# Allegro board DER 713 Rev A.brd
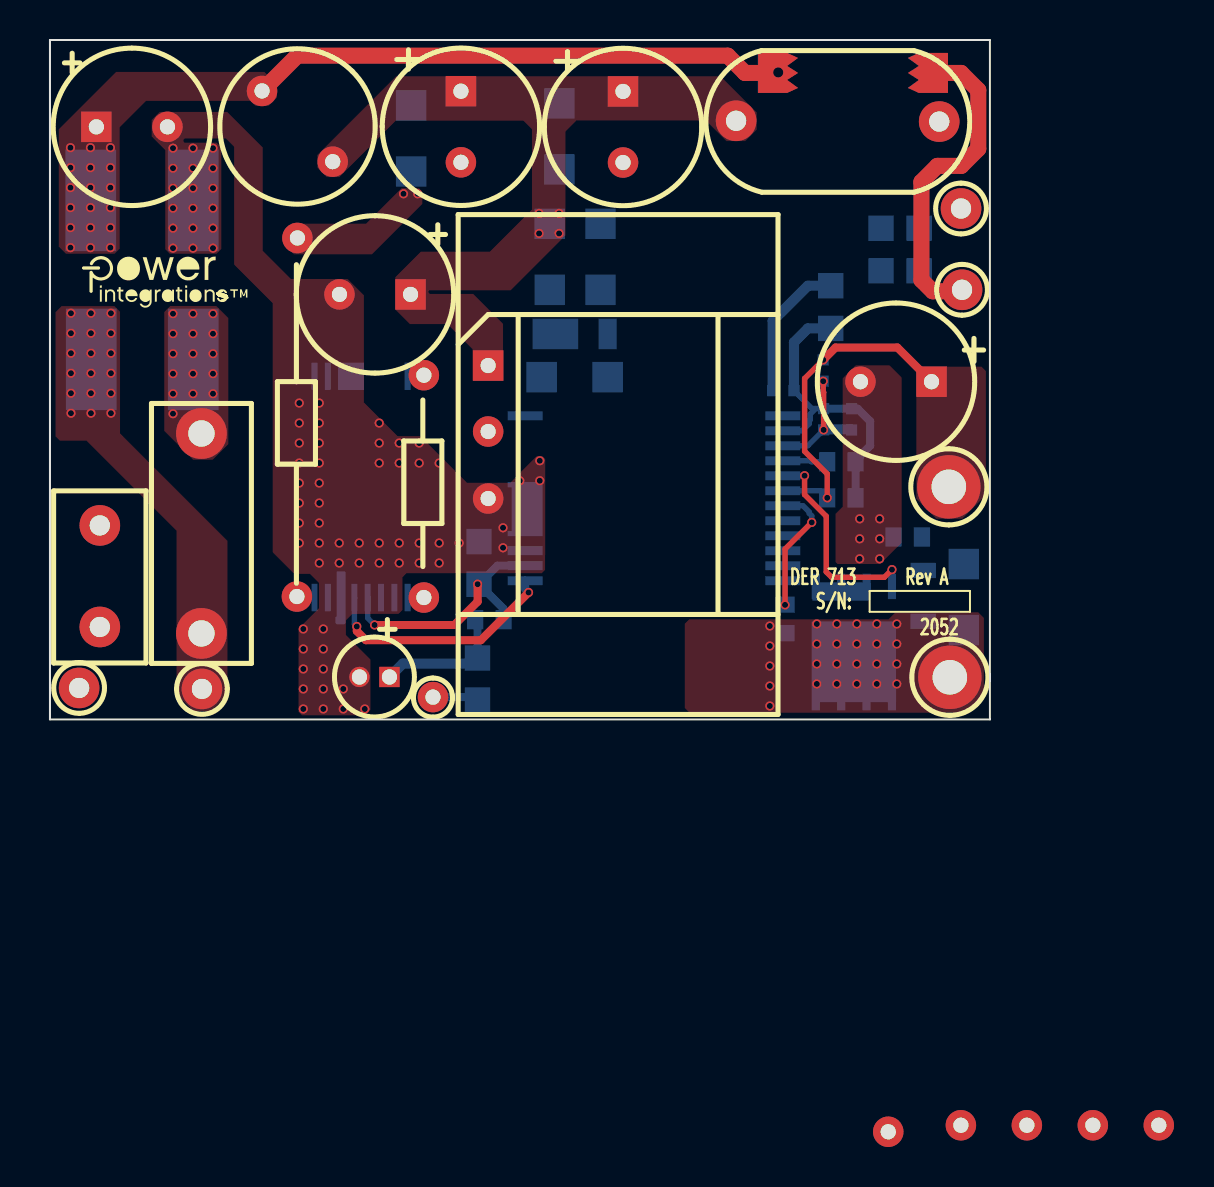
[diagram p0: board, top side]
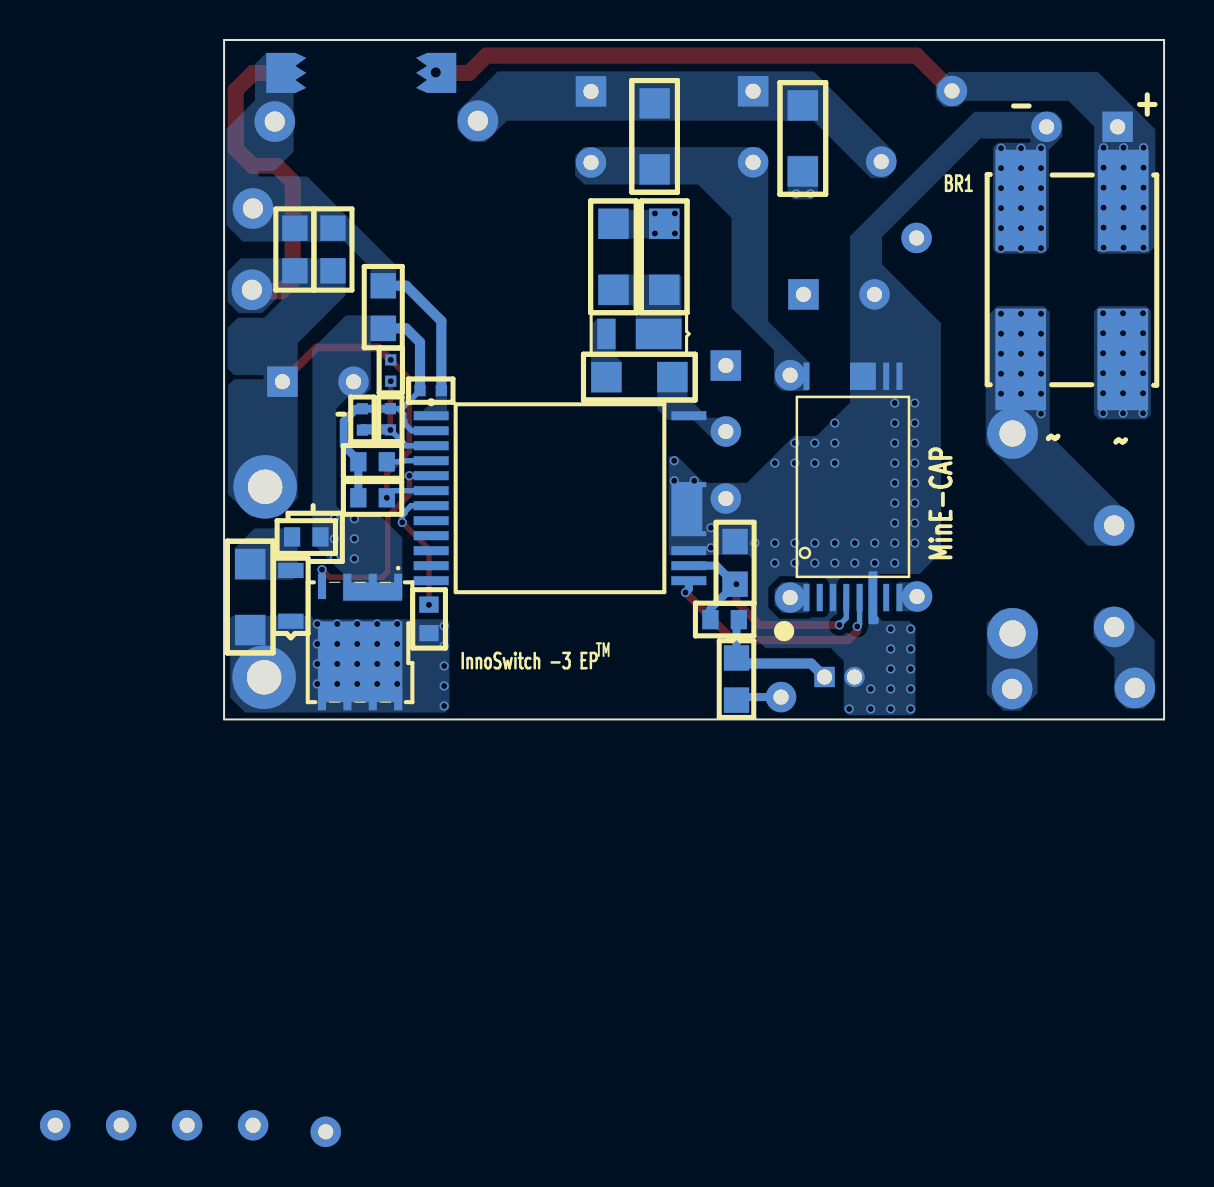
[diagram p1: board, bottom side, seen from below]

Outline 47.02 x 33.98 mm; copper layers: TOP, BOTTOM. Coordinates in mm from the lower left corner of the outline.
Outline path: 0,33.98 0,0 47.02,0 47.02,33.98 0,33.98

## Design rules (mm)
constraint set DEFAULT: min track width 0.508

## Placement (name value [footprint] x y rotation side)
BR1  Z4DGP406L-HF  [PI_SM_D_Z4D]  2.07 26.01 180 bottom
C1  0.1 uF  [PINPXCAPRAD5X13X11P1MM040]  7.58 14.3 270 top
C2  22 uF  [PIPOLCAPCLYD320LS140030]  2.32 29.64 0 top
C3  1 nF  [PINPYCAPRAD540X290LS400040]  34.33 31.19 0 top
C4  1000 pF  [PISMC1206]  25 24.79 270 bottom
C6  4.7 uF  [PISMC0805]  21.46 6.76 90 bottom
C7  1000 pF  [PISMC0603]  43.62 9.13 180 bottom
C8  820 uF  [PIPOLCAPCLYD320LS140030]  44.1 16.89 180 top
C10  2.2 uF  [PISMC0603]  40.31 12.89 180 bottom
C11  1 uF  [PISMC0603]  40.31 11.08 180 bottom
C12  1000 pF  [PISMR0402]  37.22 16.44 180 bottom
C13  1000 pF  [PISMR0402]  38.7 14.48 90 bottom
C16  22 uF  [PISMC0805]  43.48 22.44 90 bottom
C17  22 uF  [PISMC0805]  41.58 22.44 90 bottom
C18  22 uF  [PIPOLCAPCLYD320LS140030]  18.04 21.26 180 top
C19  33 uF  [PIPOLCAPCLYD320LS140030]  28.67 31.41 270 top
C21  22 uf  [PIPOLCAP4P0X11P0XLS1P5D030]  16.98 2.12 180 top
C23  33 uF  [PIPOLCAPCLYD320LS140030]  20.56 31.42 270 top
D1  DFLR1800-7  [PISMDDFLR120012]  25.26 19.28 180 bottom
D2  BAV20WS-7-F  [PISMDSOD323]  21.39 3.07 270 bottom
D4  BAV19WS  [PISMSOD323]  43.68 4.91 90 bottom
F1  3.15 A  [PI_RST_MICROFUSE]  2.5 4.62 90 top
FL1  Hole_70mils  [PI_HOLE_70MIL]  44.97 11.61 0 top
FL2  Hole_70mils  [PI_HOLE_70MIL]  45.02 2.08 0 top
FL3  Hole_30mils  [PI_HOLE_30MIL]  19.16 1.12 0 top
GND  BLK  [PITPKEYSTONE100X100]  45.58 25.55 0 top
L  BLK  [PITPKEYSTONE100X100]  1.46 1.57 0 top
L1  47 uH  [PICHOKETOKINVD345H453LS197D030]  10.61 31.43 315 top
N  WHT  [PITPKEYSTONE100X100]  7.6 1.53 90 top
NOREF  -  []  -150.78 54.23 0 top
NOREF#2  -  []  0 0 90 top
NOREF#3  -  []  1.05 23.06 0 top
NOREF#4  -  []  -228.6 -144.78 0 top
NOREF#5  -  []  0 0 0 top
Q1  AON6220  [PISMPQFN5X6B]  38.31 6.65 0 bottom
R3  2 M  [PISMR1206]  18.07 30.71 270 bottom
R4  1.8 M  [PI18WVRESD80LS100D030]  12.38 13.08 270 top
R5  24  [PISMR1206]  27.9 17.12 180 bottom
R7  470 k  [PISMR1206]  27.54 24.79 270 bottom
R8  3 k  [PISMR0603]  21.27 4.99 0 bottom
R11  10  [PISMR1206]  45.72 4.47 90 bottom
R12  47  [PISMR0603]  36.78 4.32 90 bottom
R14  0.009  [PISMR0805]  39.06 19.56 90 bottom
R15  169.0 k  [PISMR0402]  38.69 17.98 270 bottom
R16  11.5 k  [PISMR0402]  40.1 15.54 270 bottom
R24  3.9 M  [PISMR1206]  25.49 30.81 270 bottom
R27  1 M  [PI18WVRESD80LS100D030#2]  18.71 13.72 270 top
SG1  6.5mm gap  [PI_SPARK_GAP_6P5MM#2]  39.66 32.33 0 bottom
SG2  6.5mm gap  [PI_SPARK_GAP_6P5MM]  40.68 32.33 0 top
T2  ATQ25/16  [PI_BOBBIN_ATQ25_H_8P]  28.42 12.75 0 top
U1  INN3679C-H606  [PI_IC_INSOP_24D]  36.66 15.19 180 bottom
U4  MIN1072M  [PI_SM_MINSOP16A_1]  17.89 6.1 180 bottom
UNK20V  RED  [PITPKEYSTONE100X100]  45.63 21.49 0 top

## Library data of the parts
BR1 = DISCRETE BRIDGE_+~~-
C1 = CAP NP: alternate symbols: (pinpxcaprad5x13x11p1mm040h)
C2 C18 = CAP POL: alternate symbols: (pipolcapclyd320ls140030h630)
C3 = CAP NP: alternate symbols: (pinpycaprad540x290ls400040h,pinpycaprad500x220ls400040)
C4 C6 C7 C16 C17 = CAP NP
C8 C19 C23 = CAP POL
C10 C11 = CAP NP: alternate symbols: (pismc0603_1)
C12 C13 = CAP NP: alternate symbols: (pismr0402_1); room: 2
C21 = CAP POL: alternate symbols: (pipolcap4p0x12p5xls1p5d030h)
D1 = DIODE: room: 1
D2 = DIODE
D4 = DIODE: room: 2
F1 = FUSE: alternate symbols: (pirstmicrofusehoz); room: 1
FL1-FL3 = FlyingLead: room: 2
GND L = TESTPOINT: alternate symbols: (TP_TH_CR2_D1_1)
L1 = INDUCTOR: alternate symbols: (pichoketokinvd345h453ls197d030H)
N UNK20V = TESTPOINT
Q1 = FET_N_SGD_123_4_5678: room: 2
R3 R5 R7 R8 R11 R14 R24 = R
R4 R27 = R: alternate symbols: (pi18wresd080ls300d030)
R12 = R: alternate symbols: (pismr0603_1); room: 2
R15 R16 = R: room: 2
SG1 SG2 = SPARK_GAP
T2 = BATQ25_8P/GENERIC
U1 = Inno3EP_P15
U4 = MinE-CAP

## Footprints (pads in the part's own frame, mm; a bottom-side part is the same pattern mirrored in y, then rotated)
PI18WVRESD80LS100D030
  round 1.524 hole 0.762: 1(-11,0) 2(6.934,-0.025)
PI18WVRESD80LS100D030#2
  round 1.524 hole 0.762: 1(-3.5,0) 2(7.62,0)
PI_BOBBIN_ATQ25_H_8P
  rect 1.524x1.524 hole 0.762: 1(-6.5,4.95)
  round 1.524 hole 0.762: 2(-6.5,1.65) 3(-6.5,-1.701) 4(13.515,-33.373) 5(27.049,-33.046) 6(23.749,-33.046) 7(20.449,-33.046) 8(17.149,-33.046)
PI_HOLE_30MIL
  round 1.524 hole 0.762: 1(0,0)
PI_HOLE_70MIL
  round 3.175 hole 1.727: 1(0,0.025)
PI_IC_INSOP_24D
  rect 1.75x0.45 smd: 1(0,0) 2(0,-0.75) 3(0,-1.5) 4(0,-2.25) 5(0,-3) 6(0,-3.75) 7(0,-4.5) 8(0,-5.25) 9(0,-6) 10(0,-6.75) 11(0,-7.5) 12(0,-8.25) 13(12.89,-8.25) 14(12.89,-7.5) 15(12.89,-6.75) 24(12.89,0)
  custom 0.438x0.438 smd: 16(12.89,-4.67)
PI_RST_MICROFUSE
  round 2.032 hole 1.016: 1(0,0) 2(5.08,0)
PI_SM_D_Z4D
  rect 2.54x5.08 smd: 1(0.025,-0.051) 2(0,-8.001) 3(-5.105,-8.001) 4(-5.105,-0.051)
PI_SM_MINSOP16A_1
  rect 0.3x1.369 smd: 1(0,0) 2(0.665,0) 3(1.33,0) 4(1.995,0) 5(2.66,0) 6(3.325,0) 7(3.99,0) 8(4.655,0) 9(4.655,11.067) 10(3.99,11.067) 16(0,11.067)
  rect 1.293x1.369 smd: 11(2.829,11.067)
PI_SPARK_GAP_6P5MM
  custom 0.5x0.5 smd: 1(-4.25,0) 2(3.25,0)
PI_SPARK_GAP_6P5MM#2
  custom 0.5x0.5 smd: 1(-3.25,0) 2(4.25,0)
PICHOKETOKINVD345H453LS197D030
  round 1.524 hole 0.762: 1(0,0) 2(5.001,0)
PINPXCAPRAD5X13X11P1MM040
  round 2.54 hole 1.321: 1(0,0) 2(10,0)
PINPYCAPRAD540X290LS400040
  round 2.032 hole 1.016: 1(0,-1.25) 2(10.16,-1.29)
PIPOLCAP4P0X11P0XLS1P5D030
  rect 1.016x1.016 hole 0.762: 1(0,0)
  round 1.016 hole 0.762: 2(1.5,0)
PIPOLCAPCLYD320LS140030
  rect 1.524x1.524 hole 0.762: 1(0,0)
  round 1.524 hole 0.762: 2(3.556,0)
PISMC0603
  rect 0.813x0.965 smd: 1(0,0) 2(1.422,0)
PISMC0805
  rect 1.27x1.27 smd: 1(0,0) 2(2.134,0)
PISMC1206
  rect 1.524x1.524 smd: 1(0,0) 2(3.302,0)
PISMDDFLR120012
  rect 2.286x1.524 smd: 1(-0.025,0)
  rect 0.914x1.524 smd: 2(-2.642,0)
PISMDSOD323
  rect 1.27x1.27 smd: 1(0,0) 2(2.108,0)
PISMPQFN5X6B
  rect 0.406x1.27 smd: 1(0,0) 2(1.27,0) 3(2.54,0) 4(3.81,0)
  rect 0.406x1.219 smd: 5(3.81,5.588) 6(2.54,5.588) 7(1.27,5.588) 8(0,5.588)
PISMR0402
  rect 0.559x0.559 smd: 1(0,0) 2(1.067,0)
PISMR0603
  rect 0.813x0.965 smd: 1(0,0) 2(1.422,0)
PISMR0805
  rect 1.27x1.27 smd: 1(0,0) 2(2.134,0)
PISMR1206
  rect 1.524x1.524 smd: 1(0,0) 2(3.302,0)
PISMSOD323
  rect 0.762x1.27 smd: 1(0,0) 2(2.54,0)
PITPKEYSTONE100X100
  round 2.032 hole 1.016: 1(0,0)

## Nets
D: D4.1 FL2.1 Q1.5 Q1.6 Q1.7 Q1.8 R11.1 R12.1
NC8: U1.8
NC9: U1.9
NC10: U1.10
NC11: U1.11
NC12: U1.12
S: C7.2 C8.2 C10.1 C11.1 C12.1 C13.2 Q1.1 Q1.2 Q1.3(S3) R14.1 R16.1 U1.2
VTOP: R4.2 U4.8
N10805923: BR1.4 C2.2 C6.2 C18.2 C21.2 T2.3 U1.15 U1.16 U4.3 U4.9 U4.10 U4.11
N10806149: C6.1 R8.2 U1.14 U4.4
N10808843: C3.2 C12.2 C16.2 C17.2 GND.1 R14.2 SG1.2 U1.1
N10813018: R3.2 R4.1
N10840366: BR1.1 C2.1 L1.1 SG1.1 SG2.1
N10873526: R12.2 U1.7
N10897256: C13.1 R15.2 R16.2 U1.3
N10950053: C21.1 D2.1 R8.1
N10961861: C3.1 C4.1 C18.1 C19.1 C23.1 L1.2 R3.1 R7.1 R24.1 T2.1
N10998999: C8.1 C11.2 C16.1 C17.1 FL1.1 R15.1 SG2.2 U1.6 UNK20V.1
N11099981: BR1.3(AC2) C1.1 F1.2
N11100037: BR1.2 C1.2 N.1
N11139529: C4.2 D1.1 R7.2
N11156493: C7.1 D4.2 R11.2
N12473754: C19.2 C23.2 R24.2 R27.1 U4.16
N12473992: U1.13(VPIN) U4.5
N12493844: R5.2 T2.2 U1.24
N12496023: Q1.4 U1.5
N12509547: D1.2 R5.1
N12525421: F1.1 L.1
N12537489: R27.2 U4.1
N12549108: D2.2 FL3.1
N12562988: C10.2 U1.4

Pads without a net: T2 4 5 6 7 8; U4 2 6 7

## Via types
v1: diameter 0.457, hole 0.305, TOP to BOTTOM, 175 vias
v2: diameter 0.813, hole 0.508, TOP to BOTTOM, 1 via

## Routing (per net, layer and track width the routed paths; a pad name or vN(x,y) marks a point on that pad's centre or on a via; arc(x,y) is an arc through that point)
D:
  vias: v1(36.01,4.67) v1(36.01,3.67) v1(36.01,2.67) v1(36.01,1.67) v1(36.01,0.67) v1(38.36,4.78) v1(38.36,3.78) v1(38.36,2.78) v1(38.36,1.78) v1(39.36,4.78) v1(39.36,3.78) v1(39.36,2.78) v1(39.36,1.78) v1(40.36,4.78) v1(40.36,3.78) v1(40.36,2.78) v1(40.36,1.78) v1(41.36,4.78) v1(41.36,3.78) v1(41.36,2.78) v1(41.36,1.78) v1(42.36,4.78) v1(42.36,3.78) v1(42.36,2.78) v1(42.36,1.78)
S: length 15.5
  BOTTOM w0.27: C13.2 38.31,15.55 ; 38.31,15.55 38.12,15.55 C12.1 ; 38.31,15.55 38.04,15.28 38.04,14.99 37.98,14.94 37.98,14.79 37.64,14.44 U1.2
  BOTTOM w0.4: C11.1 C10.1 40.31,12.96 41.03,13.69 41.03,14.92 40.41,15.54 R16.1 38.71,15.54 C13.2
  BOTTOM w0.508: R14.1 37.92,19.56 37.22,18.86 C12.1
  vias: v1(40.51,10.03) v1(40.51,9.03) v1(40.51,8.03) v1(41.51,10.03) v1(41.51,9.03) v1(41.51,8.03)
N10805923:
  vias: v1(6.16,28.57) v1(6.16,27.57) v1(6.16,26.57) v1(6.16,25.57) v1(6.16,24.57) v1(6.16,23.57) v1(7.16,28.57) v1(7.16,27.57) v1(7.16,26.57) v1(7.16,25.57) v1(7.16,24.57) v1(7.16,23.57) v1(8.16,28.57) v1(8.16,27.57) v1(8.16,26.57) v1(8.16,25.57) v1(8.16,24.57) v1(8.16,23.57) v1(12.47,15.82) v1(12.47,14.82) v1(12.47,13.82) v1(12.47,12.82) v1(12.47,11.82) v1(12.47,10.82) v1(12.47,9.82) v1(12.47,8.82) v1(12.68,4.52) v1(12.68,3.52) v1(12.68,2.52) v1(12.68,1.52) v1(12.68,0.52) v1(13.47,15.82) v1(13.47,14.82) v1(13.47,13.82) v1(13.47,12.82) v1(13.47,11.82) v1(13.47,10.82) v1(13.47,9.82) v1(13.47,8.82) v1(13.47,7.82) v1(13.68,4.52) v1(13.68,3.52) v1(13.68,2.52) v1(13.68,1.52) v1(13.68,0.52) v1(14.47,8.82) v1(14.47,7.82) v1(14.68,1.52) v1(14.68,0.52) v1(15.47,8.82) v1(15.47,7.82) v1(15.75,0.52) v1(16.47,14.82) v1(16.47,13.82) v1(16.47,12.82) v1(16.47,8.82) v1(16.47,7.82) v1(17.47,13.82) v1(17.47,12.82) v1(17.47,8.82) v1(17.47,7.82) v1(18.47,13.82) v1(18.47,12.82) v1(18.47,8.82) v1(18.47,7.82) v1(19.47,12.82) v1(19.47,8.82) v1(19.47,7.82) v1(20.47,8.82) v1(22.67,9.59) v1(22.67,8.59) v1(23.5,11.94) v1(24.5,12.94) v1(24.5,11.94)
N10806149: length 13.1
  TOP w0.4: v1(16.24,4.72) 20.23,4.72 21.4,5.89 v1(21.4,6.76)
  BOTTOM w0.27: v1(16.24,4.72) 15.9,5.07 U4.4 ; C6.1 v1(21.4,6.76)
  BOTTOM w0.4: U1.14 22.39,7.69 C6.1 22.69,5.53 R8.2
N10808843: length 7.1
  BOTTOM w0.508: C12.2 36.16,19.93 37.92,21.69 R14.2
N10813018:
  vias: v1(17.69,26.29) v1(18.4,26.29)
N10840366: length 27
  TOP w0.8: SG2.1 34.77,32.33 33.91,33.2 12.37,33.2 L1.1 10.67,31.37
  vias: v1(1.03,28.6) v1(1.03,27.6) v1(1.03,26.6) v1(1.03,25.6) v1(1.03,24.6) v1(1.03,23.6) v1(2.03,28.6) v1(2.03,27.6) v1(2.03,26.6) v1(2.03,25.6) v1(2.03,24.6) v1(2.03,23.6) v1(3.03,28.6) v1(3.03,27.6) v1(3.03,26.6) v1(3.03,25.6) v1(3.03,24.6) v1(3.03,23.6) v2(36.43,32.36)
N10873526: length 6.7
  TOP w0.27: v1(36.78,5.73) 36.78,8.52 v1(38.11,9.86)
  BOTTOM w0.27: U1.7 37.67,10.69 37.98,10.38 37.98,10.32 38.11,10.19 v1(38.11,9.86)
  BOTTOM w0.508: R12.2 v1(36.78,5.73)
N10897256: length 6.2
  TOP w0.27: v1(38.69,16.92) 38.69,16.37 38.7,16.36 v1(38.7,14.48)
  BOTTOM w0.27: U1.3 36.66,13.69 37.91,13.69 v1(38.7,14.48)
  BOTTOM w0.508: R16.2 40.07,14.5 38.73,14.5 v1(38.7,14.48)
N10950053: length 6.8
  BOTTOM w0.4: D2.1 21.39,4.88 R8.1
  BOTTOM w0.508: D2.1 21.11,2.79 17.66,2.79 C21.1
N10961861:
  vias: v1(24.47,25.31) v1(24.47,24.31) v1(25.47,25.31) v1(25.47,24.31)
N10998999: length 33
  TOP w0.27: v1(38.88,11.08) 38.88,12.28 37.75,13.41 37.75,17.05 v1(38.69,17.98)
  TOP w0.4: C8.1 42.39,18.6 39.3,18.6 v1(38.69,17.98)
  TOP w0.8: UNK20V.1 45.55,21.41 44.16,21.41 43.6,21.98 43.6,26.89 44.4,27.69 45.59,27.69 46.44,28.54 46.44,31.47 45.58,32.33 SG2.2
  BOTTOM w0.27: v1(38.88,11.08) 38.53,11.44 U1.6
N11099981:
  vias: v1(6.16,20.29) v1(6.16,19.29) v1(6.16,18.29) v1(6.16,17.29) v1(6.16,16.29) v1(6.16,15.29) v1(7.16,20.29) v1(7.16,19.29) v1(7.16,18.29) v1(7.16,17.29) v1(7.16,16.29) v1(8.16,20.29) v1(8.16,19.29) v1(8.16,18.29) v1(8.16,17.29) v1(8.16,16.29)
N11100037:
  vias: v1(1.05,20.32) v1(1.05,19.32) v1(1.05,18.32) v1(1.05,17.32) v1(1.05,16.32) v1(1.05,15.32) v1(2.05,20.32) v1(2.05,19.32) v1(2.05,18.32) v1(2.05,17.32) v1(2.05,16.32) v1(2.05,15.32) v1(3.05,20.32) v1(3.05,19.32) v1(3.05,18.32) v1(3.05,17.32) v1(3.05,16.32) v1(3.05,15.32)
N12473992: length 12.2
  TOP w0.4: v1(15.35,4.65) 15.35,4.42 15.81,3.96 21.56,3.96 v1(23.94,6.35)
  BOTTOM w0.27: U4.5 15.23,4.77 v1(15.35,4.65)
  BOTTOM w0.4: U1.13 23.77,6.52 v1(23.94,6.35)
N12496023: length 10.7
  TOP w0.27: v1(37.75,12.19) 37.75,11.25 38.84,10.16 38.84,7.38 39.11,7.11 41.74,7.11 v1(42.12,7.49)
  BOTTOM w0.27: Q1.4 v1(42.12,7.49) ; U1.5 v1(37.75,12.19)
N12549108: length 2.3
  BOTTOM w0.4: D2.2 21.24,1.12 FL3.1
N12562988: length 2.2
  BOTTOM w0.27: U1.4 38.04,12.94 38.09,12.89 C10.2

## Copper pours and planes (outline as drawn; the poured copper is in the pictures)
D on BOTTOM (solid shape): 42.33,0.86 38.11,0.86 38.11,4.9 42.33,4.9
D on TOP: 45.96,0.33 46.72,1.09 46.72,5.08 46.44,5.36 42.3,5.36 41.95,5.01 31.98,5.01 31.76,4.79 31.76,0.57 32,0.33
D on BOTTOM: 46.59,5.18 46.72,5.05 46.72,1.09 45.97,0.34 35.96,0.34 35.75,0.56 35.75,4.88 35.87,5.01 42.53,5.01 42.71,5.18
S on BOTTOM (solid shape): 41.06,5.94 38.14,5.94 38.14,6.86 41.06,6.86
S on TOP: 39.66,17.06 39.66,10.64 39.3,10.28 39.3,7.88 39.41,7.77 41.54,7.77 42.48,8.71 42.61,8.84 42.61,17.11 42.01,17.71 40.31,17.71
S on BOTTOM: 38.11,5.94 38.14,5.92 41.08,5.92 41.08,7.29 42.61,8.81 42.61,18.53 40.93,20.21 38.45,20.21 38.41,20.17 38.41,18.92 39.68,18.92 39.68,16.54 40.09,16.13 40.83,16.13 41.41,15.54 41.41,10.69 40.93,10.21 39.23,10.21 38.11,9.09
VTOP on BOTTOM: 13.37,6.78 13.37,5.41 12.15,5.41 11.69,5.87 11.69,6.45 12.1,6.86 13.29,6.86
N10805923 on BOTTOM (solid shape): 14.79,7.35 14.79,4.82 14.73,4.76 14.35,4.76 14.27,4.84 14.27,5.1 14.35,5.17 14.35,7.41 14.73,7.41
N10805923 on TOP: 24.77,13.03 24.77,8.23 24.77,8.23 24.77,7.49 24.6,7.31 17.84,7.31 17.63,7.11 17.63,5.47 17.43,5.28 15.13,5.28 14.81,4.95 14.81,4.23 16.03,3 16.03,0.47 15.77,0.2 12.61,0.2 12.44,0.38 12.44,4.54 13.46,5.56 13.46,6.82 13.01,7.28 12.23,7.28 11.14,8.36 11.14,20.81 11.15,20.81 9.81,22.15 9.21,22.75 9.21,28.64 8.8,29.06 6.75,29.06 6.68,28.98 6.68,28.91 6.75,28.84 8.34,28.84 8.57,28.61 8.57,23.53 8.33,23.29 6,23.29 5.77,23.52 5.77,28.48 5.09,29.16 5.09,29.98 5.49,30.39 8.87,30.39 10.64,28.61 10.64,23.44 12.06,22.03 14.89,22.03 15.7,21.22 15.7,15.85 17.38,14.17 18.32,14.17 18.32,14.17 18.53,14.17 20.86,11.84 23.02,11.84 24.34,13.16 24.65,13.16
N10805923 on BOTTOM: 15.71,15.85 17.38,14.17 18.53,14.17 20.86,11.84 23.02,11.84 24.34,13.16 24.77,13.16 24.77,8.23 20.79,8.23 20.48,7.93 20.48,4.11 19.93,3.56 16.67,3.56 16.03,2.92 16.03,0.47 15.77,0.2 12.61,0.2 12.44,0.38 12.44,4.61 12.75,4.93 14.1,4.93 14.35,5.17 14.35,7.16 14.23,7.28 12.23,7.28 11.16,8.35 11.16,19.81 11.67,20.32 14.11,22.76 14.11,24.13 9.56,28.68 9.18,29.05 6.74,29.05 6.67,28.98 6.67,28.92 6.74,28.84 8.33,28.84 8.56,28.61 8.56,23.52 8.33,23.29 6.02,23.29 5.77,23.55 5.77,28.48 5.09,29.16 5.09,29.98 5.5,30.39 9.49,30.39 15.71,24.17
N10808843 on BOTTOM: 35.87,15.01 37.45,15.01 37.45,15.39 37.12,15.39 36.43,16.08 36.43,16.71 35.87,16.71
N10808843 on BOTTOM: 46.09,23.9 46.9,24.71 46.9,29.54 45.48,30.96 45.48,32.78 44.93,33.33 43.66,33.33 43.55,33.22 43.55,28.4 44.49,27.46 45.22,27.46 45.32,27.36 45.32,27.23 45.25,27.15 42.86,27.15 38.41,22.71 38.41,21.06 39.68,21.06 39.68,22.58 41.01,23.9
N10813018 on TOP: 11.82,24.49 11.82,23.65 12.2,23.27 16.11,23.27 18.63,25.78 18.63,26.39 18.45,26.57 17.59,26.57 15.81,24.79 12.13,24.79
N10813018 on BOTTOM: 18.81,28.19 18.83,28.17 18.83,26.29 18.55,26.01 17.61,26.01 17.31,26.31 17.31,28.17 17.33,28.19
N10840366 on TOP: 3.49,23.55 3.49,29.62 4.81,30.94 9.96,30.94 9.96,30.93 10.03,30.93 10.27,30.7 10.95,30.7 11.36,31.11 11.36,31.75 11.32,31.79 10.73,32.38 3.31,32.38 0.44,29.51 0.44,23.65 0.79,23.3 0.79,23.29 3.24,23.29
N10840366 on BOTTOM: 0.44,23.65 0.44,29.51 3.31,32.38 10.78,32.38 11.42,31.75 11.42,31.04 11.01,30.63 10.28,30.63 9.98,30.94 4.79,30.94 3.49,29.64 3.49,23.55 3.24,23.29 0.8,23.29
N10961861 on TOP: 22.67,16.94 21.14,16.94 21.14,18.52 19.89,19.77 18.01,19.77 17.28,20.5 17.28,22.12 18.55,23.39 22.01,23.39 24.11,25.5 24.11,29.51 23.68,29.95 17.3,29.95 14.48,27.12 13.85,27.12 13.38,27.59 13.38,28.23 17.32,32.17 33.54,32.17 35.36,30.35 35.36,29.5 34.78,28.92 33.85,28.92 32.81,29.96 26.34,29.96 25.79,29.41 25.79,24.21 23.05,21.46 18.98,21.46 18.93,21.41 18.93,21.36 19.01,21.29 21.17,21.29 22.67,19.79
N10961861 on BOTTOM: 24.42,25.48 28.13,25.48 28.25,25.35 28.25,24.16 28.15,24.05 24.37,24.05 24.29,24.13 24.29,25.35
N10961861 on BOTTOM: 33.32,32.41 35.36,30.38 35.36,29.52 34.72,28.88 33.93,28.88 32.87,29.95 18.07,29.95 18.07,29.94 17.54,29.94 14.67,27.07 13.88,27.07 13.42,27.53 13.42,28.3 17.53,32.41
N10998999 on TOP: 46.82,17.42 46.6,17.64 43.34,17.64 43.34,11.04 44.35,10.04 45.64,10.04 46.82,11.22
N10998999 on BOTTOM: 43.34,18.82 43.34,11.05 44.25,10.15 45.71,10.15 46.82,11.26 46.82,16.71 46.52,17.02 45.09,17.02 45.04,17.07 45.04,17.17 45.09,17.22 46.52,17.22 46.85,17.55 46.85,19.58 46.34,20.09 45.02,20.09 44.15,20.96 44.15,21.35 44.24,21.44 44.29,21.44 44.38,21.35 44.38,21.06 45.12,20.32 46.29,20.32 46.85,20.88 46.85,22.4 46.19,23.06 40.95,23.06 40.95,21.21
N11099981 on TOP: 8.14,12.99 7.16,12.99 5.72,14.44 5.72,20.37 6.02,20.68 8.33,20.68 8.92,20.08 8.92,13.77
N11099981 on BOTTOM: 3.82,8.69 8.04,12.9 8.04,12.9 8.92,13.78 8.92,20.09 8.33,20.68 6.02,20.68 5.71,20.37 5.71,14.24 1.56,10.08 1.56,9.19 2.07,8.69
N11100037 on TOP: 1.83,13.95 6.34,9.44 6.34,1.26 7.19,0.4 7.21,0.41 8.05,0.41 8.89,1.25 8.89,8.92 3.79,14.01 3.79,14.02 3.69,14.12 3.69,14.12 3.51,14.31 3.51,20.39 3.23,20.68 0.59,20.68 0.28,20.37 0.28,14.15 0.49,13.95
N11100037 on BOTTOM: 8.19,5.49 8.87,4.8 8.87,1.27 8.04,0.43 7.2,0.43 6.33,1.3 6.33,4.85 6.97,5.49
N11100037 on BOTTOM: 0.89,15.01 3.26,15.01 3.51,15.27 3.51,20.39 3.23,20.68 0.89,20.68 0.66,20.45 0.66,15.24
N11139529 on BOTTOM: 24.25,22.25 28.3,22.25 28.3,20.73 28.3,20.73 26.65,20.73 26.42,20.5 26.43,20.49 26.43,18.52 26.42,18.52 24.14,18.52 24.14,22.14
N11156493 on BOTTOM: 46.49,6.99 46.49,8.56 45.5,9.55 43.42,9.55 43.34,9.47 43.34,7.24 43.6,6.99
N12473754 on BOTTOM: 19.8,19.91 19.67,19.77 19.33,19.43 17.75,17.86 17.75,16.55 17.74,16.54 17.84,16.43 19.14,16.43 19.52,16.81 19.52,18.47 21.64,20.59 21.64,25.08 23.31,26.76 29.01,26.76 29.46,27.21 29.46,28.2 29.03,28.63 20.25,28.63 19.8,28.18
N12493844 on BOTTOM: 21.32,14.76 21.32,14.1 21.57,13.84 22.41,13.84 23.56,14.99 24.83,14.99 25.35,15.51 25.35,17.88 23.85,17.88 23.85,17.87 23.85,16.14 22.79,15.09 21.65,15.09
N12509547 on BOTTOM: 28.36,20.04 27.44,20.04 27.44,18.19 27.14,17.89 27.14,16.36 28.67,16.36 28.67,16.36 28.67,19.73
N12525421 on BOTTOM: 3.08,5.55 2.05,5.55 0.47,3.96 0.47,1.09 1.03,0.53 1.89,0.53 2.49,1.13 2.49,3.09 3.54,4.14 3.54,5.09
N12537489 on BOTTOM: 17.74,6.78 17.74,5.44 17.84,5.33 19.11,5.33 19.49,5.71 19.49,6.48 19.11,6.86 17.82,6.86

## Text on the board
Ref Des/Silkscreen Bottom: TM | InnoSwitch -3 EP | MinE-CAP
Ref Des/Silkscreen Top: DER 713 | S/N: | Rev A | 2052
User.6: NOTES: PLEASE DELETE | 14.  FAB HOUSE LOGO,DATE CODE TO BE IN SILK SCREEN ONLY.DO NOT USE COPPER. | 13.  MATERIAL FR4 COPPER 2oz THICKNESS 0.042"
User.8: FIGURE | FINISHED_SIZE | 12.0 | 20.0 | 30.0 | 40.0 | 52.0 | 68.0 | DRILL CHART: TOP to BOTTOM | ALL UNITS ARE IN MILS | TOLERANCE_DRILL | +3.0/-3.0 | PLATED | QTY | 175 | 1 | 27 | 8 | 2
